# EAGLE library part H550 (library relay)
RELAY bistable, 1 x switch, high current
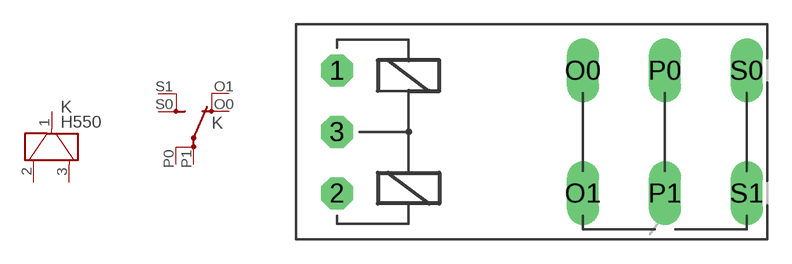
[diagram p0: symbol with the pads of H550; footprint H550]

Designator prefix K; gates 1=KD 2=UD

## H550 (OC_FARNELL: unknown; OC_NEWARK: unknown)  [H550]
1  1:1  pas
2  1:2  pas
3  1:3  pas
O0  2:O  pas
O1  2:O  pas
P0  2:P  pas
P1  2:P  pas
S0  2:S  pas
S1  2:S  pas

## Footprint H550 (pad centres in mm)
RELAY bistable, 1 x switch, high current
drill 1.321 octagon: 1 -7.62,3.81; 2 -7.62,-3.81; 3 -7.62,0
drill 1.321 long: O0 7.62,3.81; O1 7.62,-3.81; P0 12.7,3.81; P1 12.7,-3.81; S0 17.78,3.81; S1 17.78,-3.81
